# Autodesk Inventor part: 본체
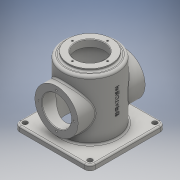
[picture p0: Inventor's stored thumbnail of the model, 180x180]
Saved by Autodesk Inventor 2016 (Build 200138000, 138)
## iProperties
Created: 2019-08
Part Number: 본체
Material: 일반
Document SubType Name: Modeling
Designer: user
Density: 1 g/cm^3
Appearance: 기본값
Mass: 414.937 g
Surface Area: 1160.05 cm^2
Volume: 414.937 cm^3
Author: user
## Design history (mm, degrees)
sketch "스케치1"
  geometry: L1 (70, -70)-(-70, -70); L2 (-70, -70)-(-70, 70); L3 (-70, 70)-(70, 70); L4 (70, 70)-(70, -70); L5 (70, -70)-(-70, 70); L6 (-70, -70)-(70, 70); 1 further point
  constraints: 12 end point, 2 midpoint, 2 parallel, 1 horizontal, 1 perpendicular
  dimensions: "d0" = 140 distance of L2.end L3.end; "d1" = 140 distance of L1.end L2.end
extrude "돌출1" new body sketch "스케치1" distance "d2" = 10; taper "d3" = 0 deg
sketch "스케치2"
  geometry: C1 r 50 at (0, 0); 1 further point
  constraints: 1 centre point, 1 coincident
  dimensions: "d4" = 100 diameter of C1
extrude "돌출2" join sketch "스케치2" distance "d5" = 110; taper "d6" = 0 deg
sketch "스케치3"
  geometry: C1 r 45 at (0, 0); 1 further point
  constraints: 1 centre point, 1 coincident
  dimensions: "d7" = 90 diameter of C1
hole "구멍1" sketch "스케치3" at (0, 0) diameter "d8" = 90; stored, may be unused: countersink angle "d12" = 90 deg, drill point angle "d14" = 0 deg; dims "d9" = 6, "d10" = 4, "d11" = 2, "d13" = 112
node "작업 평면1"
sketch "스케치5"
  geometry: L1 (-70, 0)-(70, 0) reference; L2 (70, 0)-(70, 10) reference; C1 r 40 at (0, 60); 1 further point
  constraints: 1 centre point
  dimensions: "d23" = 80 diameter of C1; "d24" = 60 distance from line of L1 C1.centre; "d25" = 70 distance from line of L2 C1.centre
extrude "돌출3" join sketch "스케치5" stored distance "d26" = 110; taper "d27" = 0 deg
hole "구멍3" diameter "d30" = 54; stored, may be unused: countersink angle "d34" = 90 deg, drill point angle "d36" = 0 deg; dims "d31" = 6, "d32" = 4, "d33" = 2, "d35" = 30, "d37" = 10, "d38" = 10
sketch "스케치6"
  geometry: L1 (0, 0)-(0, 32.5); L2 (70, -60)-(70, -50) reference; 1 further point
  constraints: 2 end point, 1 vertical
  dimensions: "d39" = 32.5 distance of L1.start L1.end; "d40" = 70 distance between parallel lines of L2 L1
hole "구멍4" sketch "스케치6" at (0, 32.5) diameter "d41" = 3.242; stored, may be unused: countersink angle "d45" = 90 deg, drill point angle "d47" = 118 deg; dims "d42" = 8, "d43" = 4, "d44" = 2, "d46" = 10
sketch "스케치7"
  geometry: C1 r 40 at (0, 0); 1 further point
  constraints: 1 centre point, 1 coincident
  dimensions: "d51" = 80 diameter of C1
extrude "돌출4" join sketch "스케치7" distance "d52" = 5; taper "d53" = 0 deg
hole "구멍5" diameter "d56" = 54; stored, may be unused: countersink angle "d60" = 90 deg, drill point angle "d62" = 0 deg; dims "d54" = 10, "d55" = 10, "d57" = 8, "d58" = 4, "d59" = 2, "d61" = 13
sketch "스케치8"
  geometry: L1 (0, 0)-(0, 32.5)
  constraints: 2 end point, 1 vertical
  dimensions: "d63" = 32.5 distance of L1.start L1.end
hole "구멍6" sketch "스케치8" at (0, 32.5) diameter "d64" = 3.242; stored, may be unused: countersink angle "d68" = 90 deg, drill point angle "d70" = 118 deg; dims "d65" = 8, "d66" = 4, "d67" = 2, "d69" = 10
node "작업 평면2"
sketch "스케치9"
  geometry: L1 (70, 0)-(-70, 0) reference; 3 further points
  constraints: 1 midpoint, 1 vertical alignment, 1 other
  dimensions: "d75" = 70 distance from line of L1 point (0, 70)
feature "엠보싱1" sketch "스케치9" dims "d0" = 140, "d1" = 140, "d76" = 0.5, "d77" = 0
fillet "모깎기1" dims "d78" = 10
hole "구멍7" diameter "d81" = 9; stored, may be unused: countersink angle "d85" = 90 deg, drill point angle "d87" = 118 deg; dims "d79" = 10, "d80" = 10, "d82" = 6, "d83" = 4, "d84" = 2, "d86" = 8
fillet "모깎기2" dims "d94" = 3
fillet "모깎기3" dims "d95" = 3
fillet "모깎기4" dims "d96" = 3
fillet "모깎기5" dims "d97" = 5
chamfer "모따기1" distance "d98" = 1; stored, may be unused: second distance "d99" = 2, angle "d100" = 45 deg
node "솔리드1"
pattern_circular "원형 패턴1" dims angle "d49" = 360 deg
mirror "대칭1"
pattern_circular "원형 패턴2" dims angle "d72" = 360 deg
pattern_linear "직사각형 패턴1" dims "d90" = 120
other parameters: "d22" = -62, "d74" = 125.25
